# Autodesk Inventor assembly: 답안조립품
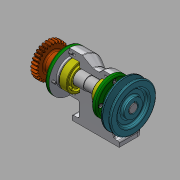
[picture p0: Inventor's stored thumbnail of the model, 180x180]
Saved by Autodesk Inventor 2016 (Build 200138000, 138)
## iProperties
Created: 2019-01
Part Number: 답안조립품
Document SubType Name: Assembly
Designer: MIRAE
Author: MIRAE
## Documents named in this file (15)
- C:\Users\MIRAE\Desktop\490107V1030\답안조립품.iam
- C:\Users\MIRAE\Desktop\490107V1030\본체.ipt
- C:\Users\MIRAE\Desktop\490107V1030\축.ipt
- C:\Users\MIRAE\Desktop\490107V1030\베어링 6203.ipt
- C:\Users\MIRAE\Desktop\490107V1030\베어링 6205.ipt
- C:\Users\MIRAE\Desktop\490107V1030\오일 실 17 30 8.ipt
- C:\Users\MIRAE\Desktop\490107V1030\오일 실 25 38 8.ipt
- C:\Users\MIRAE\Desktop\490107V1030\앞커버.ipt
- C:\Users\MIRAE\Desktop\490107V1030\뒤커버.ipt
- C:\Users\MIRAE\Desktop\490107V1030\볼트 M4.ipt
- C:\Users\MIRAE\Desktop\490107V1030\키 6 x 6 x 18.ipt
- C:\Users\MIRAE\Desktop\490107V1030\V-벨트풀리.ipt
- C:\Users\MIRAE\Desktop\490107V1030\스퍼기어.ipt
- C:\Users\MIRAE\Desktop\490107V1030\키 5 x 5 x 20.ipt
- C:\Users\MIRAE\Desktop\490107V1030\멈춤나사 M3.ipt
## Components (1 placed, 1 different names)
1. V-벨트풀리:1
